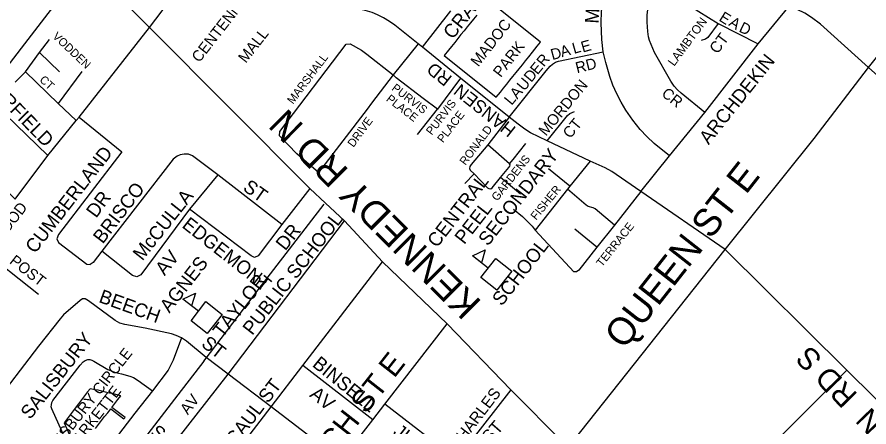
# Model space of a CAD drawing. Extents: x 586326 to 623965, y 4819854 to 4857850.
# Drawn here: x 599764 to 601319, y 4838866 to 4839615 of the extents above; entities that cross this region are included whole.
import ezdxf

# ---------------------------------------------------------------- set-up
doc = ezdxf.new("R2010")
doc.units = 0
for name, color, linetype in [('Lots_Concessions', 7, 'Continuous'), ('Major Rds and Hwys', 7, 'Continuous'), ('Major Rds Lbls', 7, 'Continuous'), ('Minor Rd Lbls', 7, 'Continuous'), ('Minor Rds', 7, 'Continuous'), ('Park Lbls', 7, 'Continuous'), ('Park Outlines', 7, 'Continuous'), ('Private Rd Lbls', 7, 'Continuous'), ('Private Rds', 7, 'Continuous'), ('Proposed Secondary Rds', 7, 'Continuous'), ('Pts of Interest', 7, 'Continuous'), ('School Syms_Lbls', 7, 'Continuous'), ('Secondary Rds Lbls', 7, 'Continuous')]:
    doc.layers.add(name, color=color, linetype=linetype)

msp = doc.modelspace()

# ---------------------------------------------------------------- linework, layer by layer
at = {"layer": 'Lots_Concessions'}
for p, q in [((599889.8, 4839711.6), (599801.7, 4839597.5)), ((599801.7, 4839597.5), (599733.2, 4839507.8)), ((600204.2, 4839116.2), (600324.7, 4839272.6)), ((600186.9, 4839093.6), (600204.2, 4839116.2)), ((600116.9, 4839001.9), (600186.9, 4839093.6)), ((600104.6, 4838986), (600116.9, 4839001.9)), ((600104.6, 4838986), (600057.3, 4838924.3)), ((600057.3, 4838924.3), (599862.4, 4838670.6))]:
    msp.add_line(p, q, dxfattribs=at)
at = {"layer": 'Major Rds and Hwys'}
for points in [[(600005.4, 4839595.2), (599640.1, 4839958.9)], [(601318.3, 4839522.6), (601455.3, 4839694.3), (601475, 4839718.9)], [(600298.1, 4839301.5), (600005.4, 4839595.2)], [(601056.4, 4839190.1), (601219.2, 4839392.6), (601318.3, 4839522.6)], [(601318.3, 4839522.6), (601404.2, 4839445.8)], [(600361.4, 4839242.4), (600327, 4839274.6), (600298.1, 4839301.5)], [(600431.3, 4839167.2), (600361.4, 4839242.4)], [(600770.4, 4838828.1), (600779.3, 4838839.3), (601056.4, 4839190.1)], [(600549.2, 4839053.9), (600431.3, 4839167.2)], [(600665.3, 4838933.2), (600549.2, 4839053.9)], [(600770.4, 4838828.1), (600762.3, 4838836.2), (600665.3, 4838933.2)]]:
    msp.add_lwpolyline(points, dxfattribs=at)
at = {"layer": 'Minor Rds'}
for points in [[(600834.2, 4839550.9), (600831.6, 4839573.4), (600830.3, 4839604), (600830.8, 4839624.6), (600834.2, 4839648.5), (600838.2, 4839669.8), (600843.6, 4839690.2), (600851.4, 4839711.1), (600861.1, 4839733.3)], [(600496.2, 4839565.8), (600453.4, 4839599.9), (600444.1, 4839606.2), (600432.8, 4839613), (600421.8, 4839618.4), (600412, 4839622.6), (600399.3, 4839626.4), (600383.3, 4839629.9), (600319, 4839640.7), (600305.1, 4839643.2), (600291.4, 4839647.1), (600282.1, 4839650.4), (600270.8, 4839655.1), (600257.4, 4839662.4), (600247.8, 4839668.6), (600238.5, 4839675.5), (600229.2, 4839683.8), (600206.4, 4839706.9)], [(601019.4, 4839440), (600976.1, 4839475.5), (600969.6, 4839481.3), (600963.7, 4839488), (600957.4, 4839497.3), (600927.5, 4839549.8), (600918.6, 4839571.6), (600916.8, 4839578.4), (600915.3, 4839588), (600914.2, 4839604.9), (600914.3, 4839618), (600915.5, 4839628.4), (600917.7, 4839639.2), (600925.3, 4839665.5), (600928.2, 4839670.5), (600931.2, 4839673.3), (600934.4, 4839675.2), (600938, 4839675.7), (600941.8, 4839675.5), (600949.2, 4839670.5), (601002, 4839628.9), (601008.6, 4839624.4), (601044.1, 4839602.5)], [(601117, 4839565.6), (601174.4, 4839635.3)], [(600504, 4839559.7), (600555.6, 4839626.1)], [(601044.1, 4839602.5), (601024.9, 4839576.9), (601020.5, 4839574.2), (601012.7, 4839571.9)], [(601044.1, 4839602.5), (601117, 4839565.6)], [(600504, 4839559.7), (600496.2, 4839565.8)], [(600573.5, 4839503), (600504, 4839559.7)], [(601019.4, 4839440), (601117, 4839565.6)], [(600662.6, 4839431.8), (600730.1, 4839516.5), (600737.4, 4839524.9), (600741.5, 4839528.7), (600746.8, 4839532), (600752.1, 4839534), (600834.2, 4839550.9)], [(600875.5, 4839444.1), (600866.8, 4839458.8), (600858.8, 4839474.1), (600851.3, 4839490.2), (600846.2, 4839505.8), (600838.7, 4839531.3), (600834.2, 4839550.9)], [(600662.6, 4839431.8), (600573.5, 4839503)], [(599760.2, 4839281.8), (599681.4, 4839359.9), (599676.6, 4839368.3), (599679.4, 4839375.6), (599728.4, 4839435), (599735.9, 4839440.4), (599742.4, 4839436.7), (599819.9, 4839361.4)], [(599876.9, 4839431.5), (599955, 4839368.1), (599839.5, 4839217.3), (599836.3, 4839209.5), (599839.5, 4839202.6), (599891.3, 4839163.1), (599897.5, 4839162.6)], [(600731.5, 4839388.6), (600701.2, 4839403.1), (600690.9, 4839409.5), (600678.5, 4839419), (600662.6, 4839431.8)], [(600731.5, 4839388.6), (600768.8, 4839434.9), (600773, 4839438.2), (600781.6, 4839441.9)], [(600954.8, 4839360.8), (600927.2, 4839383.3), (600913.5, 4839396.3), (600901.6, 4839409.3), (600888.2, 4839425.9), (600875.5, 4839444.1)], [(600954.8, 4839360.8), (601019.4, 4839440)], [(600810.5, 4839351.5), (600731.5, 4839388.6)], [(600130.2, 4839326.3), (600083.9, 4839360.9), (600076.7, 4839363.8), (600069.2, 4839364), (600061.9, 4839362.9), (600056.1, 4839360.3), (600048.8, 4839354.7), (599918.7, 4839186.9)], [(600902.8, 4839295.5), (600857.5, 4839326.8), (600849.8, 4839332.3), (600837.5, 4839338.9), (600810.5, 4839351.5)], [(600902.8, 4839295.5), (600954.8, 4839360.8)], [(600130.2, 4839326.3), (600078.7, 4839263.3)], [(600247.1, 4839235.3), (600130.2, 4839326.3)], [(600298.1, 4839301.5), (600247.1, 4839235.3)], [(601056.4, 4839190.1), (600902.8, 4839295.5)], [(600078.7, 4839263.3), (599989.7, 4839143.6), (599982.7, 4839139.6), (599974.6, 4839142), (599918.7, 4839186.9)], [(600247.1, 4839235.3), (600203.9, 4839178.4), (600197.3, 4839175.2), (600191, 4839178), (600078.7, 4839263.3)], [(600149.2, 4838962.1), (600361.4, 4839242.4)], [(599802.9, 4839107.6), (599693.6, 4839194.1)], [(599918.7, 4839186.9), (599902.8, 4839166), (599897.5, 4839162.6)], [(601056.4, 4839190.1), (601279.1, 4838969.5)], [(600285.6, 4838978), (600431.3, 4839167.2)], [(600064.3, 4839028.1), (600054.1, 4839032.7), (600045.5, 4839035.7), (599997.7, 4839045.9), (599960.5, 4839052.8), (599951.6, 4839055.3), (599942.7, 4839060), (599894.5, 4839095.8), (599888.4, 4839099.5), (599883.2, 4839099.6), (599878.8, 4839096.8), (599848.4, 4839070.4), (599842.3, 4839063.4), (599803.1, 4839012.9), (599717.5, 4838902.4)], [(600064.3, 4839028.1), (600054.1, 4839032.7), (600045.5, 4839035.7), (599997.7, 4839045.9), (599960.5, 4839052.8), (599951.6, 4839055.3), (599942.7, 4839060), (599894.5, 4839095.8), (599888.4, 4839099.5), (599883.2, 4839099.6), (599878.8, 4839096.8), (599848.4, 4839070.4), (599842.3, 4839063.4), (599803.1, 4839012.9), (599717.5, 4838902.4)], [(600064.3, 4839028.1), (600048.9, 4838987.7), (600043.1, 4838976.5), (600039.4, 4838969.4), (600010.9, 4838931.4)], [(600149.2, 4838962.1), (600108.9, 4838992.6), (600073.2, 4839022.1), (600064.3, 4839028.1)], [(599870.3, 4838802.3), (599827.3, 4838898.4), (599826.3, 4838902.3), (599826.5, 4838906), (599827.3, 4838910.1), (599829.4, 4838914.1), (599879, 4838978.5), (599884.2, 4838984.3), (599888.2, 4838987), (599892.8, 4838988.6), (599896.7, 4838988.6), (599900.3, 4838987.6), (599904, 4838985.6), (599929.8, 4838970.8), (599943.7, 4838964.9), (599954.5, 4838962.6), (599969.4, 4838958.6), (599976.5, 4838955.8), (599984.7, 4838950.3), (600010.9, 4838931.4)], [(600227.7, 4838902.3), (600285.6, 4838978)], [(600413.3, 4838878.8), (600285.6, 4838978)], [(600036.8, 4838817.6), (600149.2, 4838962.1)], [(600227.7, 4838902.3), (600149.2, 4838962.1)], [(600955.7, 4838645.7), (601279.1, 4838969.5)], [(601279.1, 4838969.5), (601529.1, 4838722.1), (601554.5, 4838637)], [(600010.9, 4838931.4), (599978.7, 4838890.6)], [(600665.3, 4838933.2), (600566.4, 4838805.8)], [(600115.1, 4838755.6), (600227.7, 4838902.3)], [(600355.4, 4838804.2), (600227.7, 4838902.3)], [(600566.4, 4838805.8), (600435.4, 4838907)], [(599978.7, 4838890.6), (599897, 4838784.3)]]:
    msp.add_lwpolyline(points, dxfattribs=at)
at = {"layer": 'Park Outlines'}
for points in [[(600603, 4839618), (600597.2, 4839610.9), (600591.5, 4839603.7), (600585.8, 4839596.6), (600580.1, 4839589.5), (600574.3, 4839582.4), (600568.6, 4839575.2), (600562.9, 4839568.1), (600557.1, 4839561), (600551.4, 4839553.9), (600543.8, 4839544.4), (600638.8, 4839468), (600646.4, 4839477.5), (600652.1, 4839484.6), (600657.9, 4839491.7), (600663.6, 4839498.9), (600669.3, 4839506), (600675.1, 4839513.1), (600680.8, 4839520.2), (600686.5, 4839527.4), (600692.3, 4839534.5), (600698, 4839541.6), (600705, 4839550.3), (600713.7, 4839561.1), (600719.7, 4839568.6), (600624.7, 4839645)], [(599907, 4838862.6), (599912.6, 4838869.9), (599918.1, 4838877.1), (599923.7, 4838884.4), (599929.3, 4838891.6), (599934.9, 4838898.9), (599959, 4838880.3), (599960.9, 4838882.7), (599936.7, 4838901.3), (599942.3, 4838908.5), (599947.9, 4838915.8), (599953.2, 4838922.7), (599943.9, 4838924.9), (599934.5, 4838927.1), (599932.3, 4838927.6), (599925.3, 4838929.3), (599915.9, 4838931.5), (599912.1, 4838932.5), (599906.7, 4838933.4), (599897, 4838935.1), (599892.7, 4838929.6), (599887.1, 4838922.3), (599881.6, 4838915.1), (599876, 4838907.8), (599868.1, 4838897.5), (599862.5, 4838890.2), (599849.5, 4838873.3), (599869.9, 4838828.1)]]:
    msp.add_lwpolyline(points, dxfattribs=at)
at = {"layer": 'Private Rds'}
for points in [[(599804.8, 4839549.5), (599823.2, 4839573.3)], [(600411.2, 4839457.2), (600402.9, 4839446.2), (600314.1, 4839330.6), (600274.5, 4839364.7), (600242.8, 4839397.6), (600243.4, 4839405.2), (600364.8, 4839565), (600371.8, 4839565.8), (600392.6, 4839553.9), (600402.5, 4839547), (600450.3, 4839508.8)], [(600496.2, 4839565.8), (600450.3, 4839508.8)], [(599779.2, 4839514.6), (599804.8, 4839549.5)], [(599804.8, 4839549.5), (599841.1, 4839514.7)], [(599760.3, 4839495.4), (599779.2, 4839514.6)], [(599838.6, 4839456.3), (599779.2, 4839514.6)], [(599882.3, 4839515), (599838.6, 4839456.3)], [(600450.3, 4839508.8), (600411.2, 4839457.2)], [(600531.3, 4839446.5), (600505.4, 4839466), (600456.1, 4839503.5), (600450.3, 4839508.8)], [(600573.5, 4839503), (600531.3, 4839446.5)], [(599872, 4839425.2), (599838.6, 4839456.3)], [(600495.2, 4839400.2), (600531.3, 4839446.5)], [(600662.6, 4839431.8), (600623.2, 4839381)], [(600663.2, 4839346.5), (600669.8, 4839354.1), (600692.8, 4839383.6)], [(600623.2, 4839381), (600593.2, 4839345.3), (600590.6, 4839341.2), (600589.9, 4839337.8), (600591.3, 4839334.6), (600598.6, 4839328.1)], [(600663.2, 4839346.5), (600623.2, 4839381)], [(600810.5, 4839351.5), (600773.1, 4839305.5)], [(600646.5, 4839321.3), (600661.6, 4839339.9), (600663.3, 4839342.3), (600664, 4839344.8), (600663.2, 4839346.5)], [(600773.1, 4839305.5), (600734.1, 4839337.2)], [(600581.6, 4839310.2), (600598.6, 4839328.1)], [(600598.6, 4839328.1), (600609.9, 4839315.9), (600623, 4839302.7), (600625.4, 4839301), (600628.9, 4839300.9), (600631.4, 4839302.6), (600646.5, 4839321.3)], [(600682.9, 4839290.8), (600646.5, 4839321.3)], [(600773.1, 4839305.5), (600768.6, 4839299.8)], [(600768.6, 4839299.8), (600709.7, 4839225)], [(600854.6, 4839234.5), (600819.6, 4839264.2), (600815.4, 4839266.2), (600806.8, 4839268.5), (600803, 4839270.8), (600768.6, 4839299.8)], [(600902.8, 4839295.5), (600854.6, 4839234.5)], [(600670.2, 4839263.4), (600686.5, 4839250.3), (600704.1, 4839232.5), (600709.7, 4839225)], [(600822.5, 4839194.3), (600782.3, 4839226.8)], [(600854.6, 4839234.5), (600822.5, 4839194.3)], [(600822.5, 4839194.3), (600789.7, 4839152.2), (600785.1, 4839149), (600780.1, 4839148.7), (600709.7, 4839225)]]:
    msp.add_lwpolyline(points, dxfattribs=at)
at = {"layer": 'Proposed Secondary Rds'}
for points in [[(600005.4, 4839595.2), (600017, 4839610.4), (600030.8, 4839628.5), (600141.9, 4839771)], [(601318.3, 4839522.6), (601231, 4839601.5), (601214.1, 4839613.7), (601202.1, 4839621.4), (601174.4, 4839635.3)], [(599876.9, 4839431.5), (600005.4, 4839595.2)], [(599872, 4839425.2), (599876.9, 4839431.5)], [(599819.9, 4839361.4), (599872, 4839425.2)], [(599760.2, 4839281.8), (599819.9, 4839361.4)], [(600435.4, 4838907), (600549.2, 4839053.9)], [(600413.3, 4838878.8), (600435.4, 4838907)], [(600355.4, 4838804.2), (600413.3, 4838878.8)]]:
    msp.add_lwpolyline(points, dxfattribs=at)
at = {"layer": 'School Syms_Lbls'}
for p, q in [((600624, 4839155.8), (600595.6, 4839178)), ((600095, 4839077), (600066.6, 4839099.2))]:
    msp.add_line(p, q, dxfattribs=at)
for points in [[(600595.6, 4839178), (600618.4, 4839189.1), (600611.5, 4839165.6)], [(600610.4, 4839138.4), (600637.7, 4839173.3), (600667.3, 4839150.2), (600640, 4839115.3)], [(600066.6, 4839099.2), (600089.4, 4839110.2), (600082.5, 4839086.7)], [(600081.4, 4839059.6), (600108.7, 4839094.5), (600138.3, 4839071.3), (600111, 4839036.4)]]:
    msp.add_lwpolyline(points, close=True, dxfattribs=at)

# ---------------------------------------------------------------- texts
at = {"layer": 'Major Rds Lbls'}
for s, height, rotation, p in [('KENNEDY RD N', 49.998, 135.1861, (600613.7, 4839093.7)), ('QUEEN ST E', 50, 51.8566, (600872, 4839005.4))]:
    msp.add_text(s, height=height, rotation=rotation, dxfattribs=at).set_placement(p)
at = {"layer": 'Minor Rd Lbls'}
for s, height, rotation, p in [('CRAWFORD DR', 25.002, 51.5362, (600559.2, 4839572.4)), ('M', 25, 86.4237, (600825.5, 4839602.1)), ('E', 20, 327.7713, (601043.8, 4839608.9)), ('LAMBTON', 15.92, 53.4712, (600963.5, 4839523.6)), ('A', 20, 327.7713, (601061.7, 4839599.9)), ('D', 20, 334.204, (601080.4, 4839588.6)), ('CT', 20.59, 53.4712, (601042.7, 4839545.8)), ('E', 20, 15.6682, (600796.6, 4839549.5)), ('D', 20, 15.6682, (600741.2, 4839535.7)), ('A', 20, 15.6682, (600758.6, 4839541)), ('L', 20, 15.6682, (600780.6, 4839547.1)), ('R', 20, 50.4404, (600725.7, 4839522.3)), ('RD', 20, 14.226, (600786.2, 4839511.7)), ('ARCHDEKIN', 25, 51.4578, (601026.5, 4839380.1)), ('HANSEN  RD ', 23.617, 141.4278, (600676.4, 4839411.9)), ('E', 20, 50.4404, (600714, 4839507.9)), ('GARFIELD', 25, 314.2927, (599698.4, 4839494.9)), ('D', 20, 50.4404, (600702.6, 4839494)), ('U', 20, 50.4404, (600689.9, 4839478.2)), ('MORDON', 20, 50.4404, (600729.6, 4839395.8)), ('A', 20, 50.4404, (600677, 4839463.6)), ('CR', 20, 321.0614, (600939, 4839471.9)), ('L', 20, 50.4404, (600666.8, 4839452.1)), ('CT', 20, 50.4404, (600773.8, 4839391.3)), ('CUMBERLAND', 25, 52.2607, (599796.5, 4839181)), ('BRISCO', 24.98, 52.5373, (599920.3, 4839198.7)), ('ST', 25, 324.6481, (600174.5, 4839299.1)), ('DR', 25, 53.6526, (599908.1, 4839245.9)), ('McCULLA', 25, 51.5212, (599992.6, 4839167.9)), ('EDGEMONT', 25, 321.7901, (600063.3, 4839231.4)), ('DR', 25, 51.5778, (600253.5, 4839186.2)), ('POST', 20, 322.2243, (599748.6, 4839165.7)), ('AV', 25, 50.9062, (600033.2, 4839140.7)), ('BEECH', 25, 340.1554, (599911.5, 4839094.1)), ('SALISBURY', 25, 51.9085, (599787.8, 4838877.9)), ('ST', 25, 322.3861, (600098.4, 4839014.3)), ('HANSEN  RD S', 39.996, 134.3462, (601476.9, 4838744.3)), ('BINSELL', 25, 320.9806, (600301.3, 4838977.4)), ('McCAUL ST', 25, 52.5903, (600135.2, 4838793.8)), ('AV', 25, 320.9806, (600296.5, 4838922.1)), ('CHARLES', 20.85, 52.5083, (600568.2, 4838822.5)), ('WOODWARD           AV', 20.364, 52.2803, (599920.2, 4838685.5)), ('JUNE', 25, 322.1843, (600448.5, 4838853.1)), ('ST', 23.06, 49.0743, (600627.4, 4838834.3)), ('SOPHIA ST', 25, 321.8428, (600005.2, 4838852.1))]:
    msp.add_text(s, height=height, rotation=rotation, dxfattribs=at).set_placement(p)
at = {"layer": 'Park Lbls'}
for s, height, p in [('MADOC', 19.99, (600605.9, 4839522.4)), ('PARK', 19.99, (600646.9, 4839503)), ('LOCUSTWOOD', 19.99, (599664, 4839113.1)), ('SALISBURY CIRCLE', 19.992, (599818.2, 4838798.4)), ('PARKETTE', 19.99, (599868.3, 4838819.6))]:
    msp.add_text(s, height=height, rotation=52, dxfattribs=at).set_placement(p)
at = {"layer": 'Private Rd Lbls'}
for s, rotation, p in [('VODDEN', 316.6194, (599827.4, 4839577.7)), ('MARSHALL', 53.0113, (600267.6, 4839454.3)), ('CT', 316.4688, (599803.6, 4839498.4)), ('PURVIS', 322.3738, (600446.5, 4839482.2)), ('PLACE', 322.3413, (600436.5, 4839462.4)), ('PURVIS', 52.3738, (600521, 4839397.6)), ('DRIVE', 53.7676, (600378, 4839375.4)), ('PLACE', 52.3413, (600541.5, 4839383.7)), ('RONALD', 53.0651, (600582.4, 4839342.6)), ('GARDENS', 51.6667, (600640.4, 4839277.1)), ('FISHER', 50.839, (600711.6, 4839242.4)), ('TERRACE', 51.571, (600831.8, 4839156.9))]:
    msp.add_text(s, height=15, rotation=rotation, dxfattribs=at).set_placement(p)
at = {"layer": 'Pts of Interest'}
for s, p in [('CENTENNIAL', (600096.5, 4839530.1)), ('MALL', (600181.5, 4839529.1))]:
    msp.add_text(s, height=19.99, rotation=52, dxfattribs=at).set_placement(p)
at = {"layer": 'School Syms_Lbls'}
for s, p in [('SECONDARY', (600623.6, 4839194.7)), ('CENTRAL ', (600530.3, 4839191.6)), ('PEEL', (600580.2, 4839197.7)), ('PUBLIC SCHOOL', (600193.2, 4839031.7)), ('SCHOOL', (600648.8, 4839085.1)), ('AGNES', (600041.9, 4839072.5)), ('TAYLOR', (600138.8, 4839027.3))]:
    msp.add_text(s, height=25, rotation=52, dxfattribs=at).set_placement(p)
at = {"layer": 'Secondary Rds Lbls'}
msp.add_text('CHURCH ST E', height=40.002, rotation=51.9152, dxfattribs=at).set_placement((600248.9, 4838693.7))

doc.saveas('drawing.dxf')
